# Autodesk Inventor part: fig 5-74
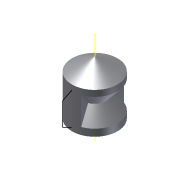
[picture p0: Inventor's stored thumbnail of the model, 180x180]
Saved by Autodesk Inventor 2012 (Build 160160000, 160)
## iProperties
Created: 2004-05
Part Number: fig 5-74
Document SubType Name: Modeling
Designer: CADCIM Technologies
Manufacturer: Standard
Standards Organization: Custom
Density: 1 g/cm^3
Material: Default
Author: CADCIM Technologies
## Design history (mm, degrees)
sketch "Sketch1"
  geometry: L1 (0, -21.51)-(0, 21.51); L2 (0, 21.51)-(-14.639, 13.059); L3 (-14.639, 13.059)-(-14.639, -13.059); L4 (-14.639, -13.059)-(0, -21.51); 2 further points
  constraints: 8 end point, 1 coincident, 1 equal length, 1 midpoint, 1 parallel, 1 vertical, 1 other
  dimensions: "d3" = 120 deg angle of L4 L3
revolve "Revolution1" sketch "Sketch1" stored, may be unused: angle "d0" = 90 deg
workaxis "Work Axis1"
sketch "Sketch2"
  geometry: L1 (-15.658, 10.423)-(-7.144, 0); L2 (-7.144, 0)-(-15.658, -9.738); L3 (-15.658, -9.738)-(-15.658, 10.423); L4 (0, -25.812)-(0, 34.416) reference
  constraints: 6 end point, 1 vertical
revolve "Revolution2" sketch "Sketch2" stored, may be unused: angle "d4" = 140 deg
sketch "Sketch3"
  geometry: L1 (-14.955, 9.983)-(-20.736, 7.191); L2 (-20.736, 7.191)-(-20.736, -7.686); L3 (-20.736, -7.686)-(-15, -10.57); L4 (0, -25.812)-(0, 34.416) reference
  constraints: 6 end point, 1 equal length, 1 vertical
body "Solid1"
